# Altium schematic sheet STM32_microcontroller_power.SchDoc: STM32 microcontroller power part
size A4; Date: Not used; ApprovedBy: Not used; CheckedBy: Not used; Author: Not used; CompanyName: STMicroelectronics; DrawnBy: Not used; Engineer: Not used; Organization: Not used; Address1: Not used; Address2: Not used; Address3: Not used; Address4: Not used; DocumentNumber: 4; Revision: Not used; SheetNumber: 4; SheetTotal: 8
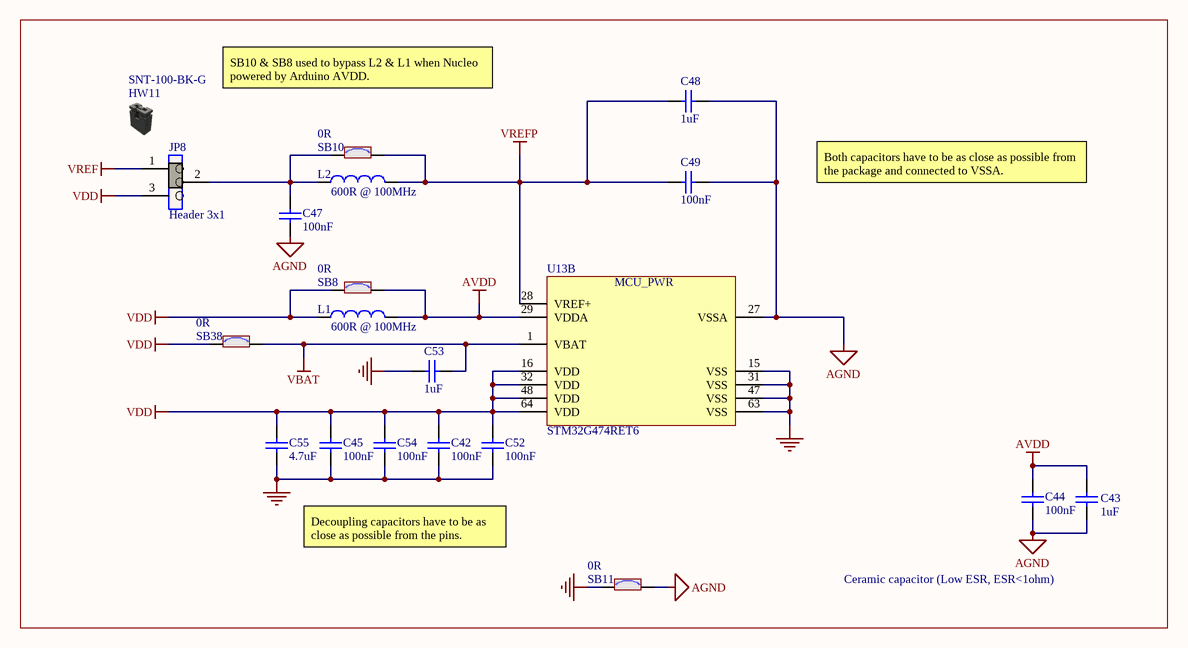
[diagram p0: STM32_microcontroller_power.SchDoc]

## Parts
C42  value 100nF  [C0402]  (hidden comment: Capacitor)
C43  value 1uF  [C0603]
C44  value 100nF  [C0402]  (hidden comment: Capacitor)
C45  value 100nF  [C0402]  (hidden comment: Capacitor)
C47  value 100nF  [C0402]  (hidden comment: Capacitor)
C48  value 1uF  [C0603]
C49  value 100nF  [C0402]  (hidden comment: Capacitor)
C52  value 100nF  [C0402]  (hidden comment: Capacitor)
C53  value 1uF  [C0603]
C54  value 100nF  [C0402]  (hidden comment: Capacitor)
C55  value 4.7uF  [C0603]
HW11  value SNT-100-BK-G  (mechanical)
JP8  value Header 3x1  [CON_SAMTEC_TSW-103-07-F-S]
L1  value 600R @ 100MHz  [L0603]
L2  value 600R @ 100MHz  [L0603]
SB8  value 0R  [SOLDER-BRIDGE_R0603-0R]
SB10  value 0R  [SOLDER-BRIDGE_R0603-0R]
SB11  value 0R  [SOLDER-BRIDGE_R0603-0R]
SB38  value 0R  [SOLDER-BRIDGE_R0603-0R]
U13  value STM32G474RET6  [ICC_LQFP64_10X10_P050_SOCKET_YAMAICHI_IC149-064-069-B5_NM]  (part B of 2)

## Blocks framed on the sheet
Ceramic capacitor (Low ESR, ESR<1ohm): C42-C45 C47-C49 C52-C55 HW11 JP8 L1 L2 SB8 SB10 SB11 SB38 U13

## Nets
AGND: C43.1 C44.1 C47.1 C48.2 C49.2 SB11.2 U13.27(VSSA)
AVDD: C43.2 C44.2 L1.2 SB8.2 U13.29(VDDA)
GND: C42.1 C45.1 C52.1 C53.1 C54.1 C55.1 SB11.1 U13.15(VSS) U13.31(VSS) U13.47(VSS) U13.63(VSS)
VBAT: C53.2 SB38.2 U13.1(VBAT)
VDD: C42.2 C45.2 C52.2 C54.2 C55.2 JP8.3 L1.1 SB8.1 SB38.1 U13.16(VDD) U13.32(VDD) U13.48(VDD) U13.64(VDD)
VREF: JP8.1
VREFP: C48.1 C49.1 L2.2 SB10.2 U13.28(VREF+)
NetC47_2: C47.2 JP8.2 L2.1 SB10.1

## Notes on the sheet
- SB10 & SB8 used to bypass L2 & L1 when Nucleo powered by Arduino AVDD.
- Both capacitors have to be as close as possible from the package and connected to VSSA.
- Decoupling capacitors have to be as close as possible from the pins.

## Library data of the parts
C42 C44 C45 C47 C49 C52 C54 = MCD-00006: Capacitor, MLCC, 100nF, 16V, X7R, +/-10%, 0402, T=0.5mm; Manufacturer_Part_Number: CC0402KRX7R7BB104; Manufacturer: YAGEO; Part_Preference: Recommended; Partial_Alternate_Internal_Part_Number: MCD-03299; Order_Code_RS: 9402047; Component_Country_Of_Origin: China; ShowFields: YES; ID: 2474
C43 C48 C53 = MCD-00010: Capacitor, MLCC, 1uF, 16V, X5R, 10%, 0603, T=0,8mm; Manufacturer_Part_Number: CC0603KRX5R7BB105; Manufacturer: YAGEO; Part_Preference: Recommended; Provided_By: Subcon; Initial_Board_Reference: MB1274; Component_Country_Of_Origin: China; ID: 2470; Order_Code_RS: 2370680; ShowFields: YES
C55 = MCD-00009: Capacitor, MLCC, 4.7uF, 16V, X5R, 10%, 0603, T=0.8mm; Manufacturer_Part_Number: CC0603KRX5R7BB475; Manufacturer: YAGEO; Part_Preference: Recommended; Partial_Alternate_Internal_Part_Number: MCD-03565; Provided_By: subcon; Initial_Board_Reference: MB1274; Alternate_EMS: A; Component_Country_Of_Origin: China; ID: 2471; ShowFields: YES
HW11 = MCD-00043: SHUNT 2.54mm BLACK; Manufacturer: SAMTEC; Part_Type: Misc; Manufacturer_HQ_COO: Unknown; Part_Preference: Recommended; Partial_Alternate_Internal_Part_Number: MCD-01849, MCD-01864, MCD-02388, MCD-03991, MCD-04284, MCD-04580; Provided_By: Subcon; Initial_Board_Reference: MB1274; Alternate_EMS: A; Component_Country_Of_Origin: China, Costa Rica, Malaysia, USA, Vietnam; ID: 2551; Order_Code_RS: 158-7784; ShowFields: YES
JP8 = MCD-00684: Header, 3x1, 2,54mm, VR, TH, Height 5.84mm/2.54mm - Shunt Fitted 1-2 by default; Part_Type: Connector; Manufacturer_Part_Number: TSW-103-07-F-S; Manufacturer: SAMTEC; Part_Preference: Recommended; Partial_Alternate_Internal_Part_Number: MCD-03595, MCD-03723, MCD-03849, MCD-03980, MCD-04583; Provided_By: SUBCO; Component_Country_Of_Origin: China, Costa Rica, Malaysia, USA, Vietnam; ID: 3059; Order_Code_RS: 161-2248; ShowFields: YES
L1 L2 = MCD-00047: SMD Chip ferrite bead, 600R@100MHz +/-25%, 350mA, 500mohm DC, 0603, T=0.8mm; Part_Type: Inductor; Manufacturer_Part_Number: FCM1608KF-601T03; Manufacturer: TAI-TECH; Part_Preference: Recommended; Partial_Alternate_Internal_Part_Number: MCD-02959; Provided_By: SUBCO; Component_Country_Of_Origin: Unknown; ID: 2546; ShowFields: YES
SB8 SB10 SB11 SB38 = MCD-00071: Solder Bridge ON; Part_Type: Resistor; Manufacturer_Part_Number: RC0603JR-070RL; Manufacturer: YAGEO; Manufacturer_HQ_COO: Unknown; Part_Preference: Recommended; Provided_By: SUBCO; Component_Country_Of_Origin: China; ID: 2521; Order_Code_RS: 199-5647; ShowFields: YES
U13 = MCD-01243: STM32G474, LQFP64 package,  3D IC footprint with 2D socket footprint.; Manufacturer: STMICROELECTRONICS; BMS_Part_Number: 9175326; Manufacturer_HQ_COO: EU; Part_Preference: Recommended; Provided_By: SUBCO with ST control; ECCN_US: 3A991A2; ECCN_EU: NEC; Component_Country_Of_Origin: China; ID: 3257; Order_Code_RS: 193-9861; ShowFields: YES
